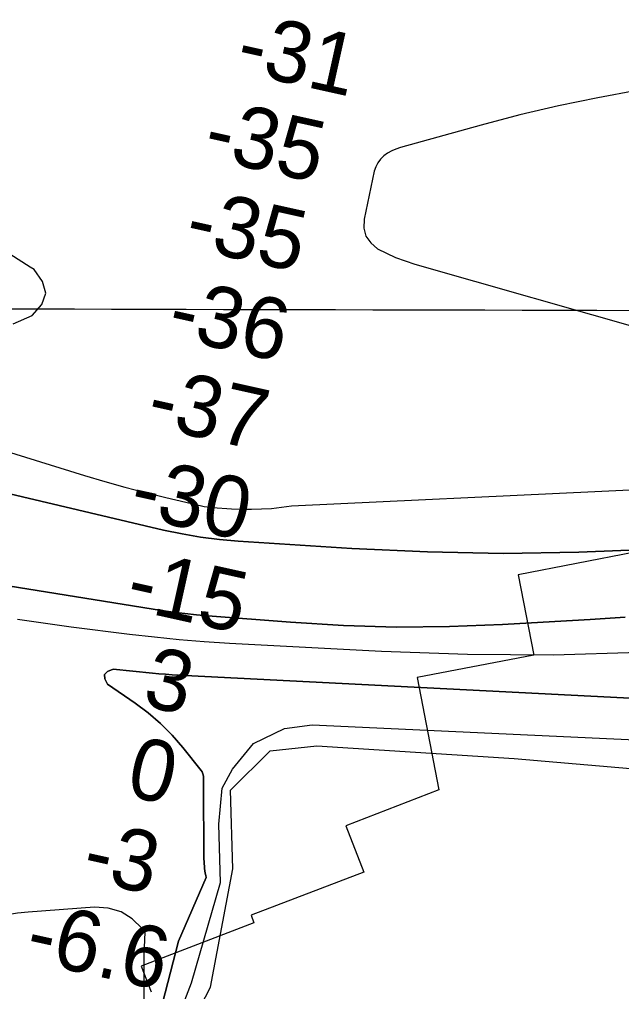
# Model space of a CAD drawing. Extents: x 3161615 to 3199515, y 867541 to 892976.
# Drawn here: x 3188892 to 3189551, y 878257 to 879321 of the extents above; entities that cross this region are included whole.
import ezdxf

# ---------------------------------------------------------------- set-up
doc = ezdxf.new("R2010")
doc.units = 0
for name, color, linetype in [('V-GRID-MAJR', 7, 'Continuous'), ('V-RIVR-RANG', 7, 'Continuous'), ('V-RRAP-RVMT', 7, 'Continuous'), ('V-TOPO-DPTH', 7, 'Continuous'), ('V-TOPO-MAJR', 7, 'Continuous'), ('V-TOPO-MINR', 7, 'Continuous'), ('V-TOPO-WATR', 7, 'Continuous')]:
    doc.layers.add(name, color=color, linetype=linetype)

msp = doc.modelspace()

# ---------------------------------------------------------------- linework, layer by layer
at = {"layer": 'V-GRID-MAJR'}
msp.add_spline([(3165838.644, 879070.158), (3171065.6580000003, 879053.813), (3176292.6750000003, 879038.2270000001), (3181519.694, 879023.402), (3186746.716, 879009.337), (3191973.739, 878996.033), (3197200.764, 878983.488), (3197200.765, 878983.488)], degree=3, dxfattribs=at)
at = {"layer": 'V-RRAP-RVMT'}
for p, q in [((3189565.0620000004, 878737.9829999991), (3189437.496000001, 878713.1959999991)), ((3189437.496000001, 878713.1959999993), (3189454.570000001, 878625.2389999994)), ((3189454.5700000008, 878625.2389999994), (3189326.954000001, 878600.6169999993)), ((3189326.954000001, 878600.616999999), (3189350.876000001, 878477.5729999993)), ((3189350.876000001, 878477.5729999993), (3189249.0130000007, 878438.148999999)), ((3189249.0130000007, 878438.148999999), (3189268.5090000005, 878387.773999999)), ((3189268.509000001, 878387.773999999), (3189145.2030000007, 878340.476999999)), ((3189148.2570000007, 878332.1869999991), (3189025.0790000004, 878284.8169999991)), ((3189145.2030000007, 878340.476999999), (3189148.2570000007, 878332.1869999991)), ((3189025.0790000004, 878284.8169999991), (3189036.0170000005, 878256.7379999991))]:
    msp.add_line(p, q, dxfattribs=at)
at = {"layer": 'V-TOPO-DPTH'}
for points in [[(3188203.1891735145, 879179.2378905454), (3188433.301359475, 878925.2373128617), (3188445.571534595, 878917.5798306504), (3188458.2858328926, 878910.6848433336), (3188471.2962133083, 878904.2981859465), (3188484.667643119, 878898.6978247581), (3188498.2204028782, 878893.6289504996), (3188512.0451575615, 878889.3573066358), (3188526.051242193, 878885.6171497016), (3189049.484469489, 878762.0639388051), (3189069.719366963, 878757.8251826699), (3189090.0565771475, 878754.2748056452), (3189110.5472563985, 878751.7569972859), (3189131.140248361, 878749.9275680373), (3189255.383497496, 878742.0529966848), (3189338.179173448, 878738.3195993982), (3189420.9799930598, 878736.5986324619), (3189503.788528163, 878737.8963110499), (3189586.602206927, 878741.2064199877)], [(3189586.602206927, 878741.2064199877), (3189503.788528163, 878737.8963110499), (3189420.9799930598, 878736.5986324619), (3189338.179173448, 878738.3195993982), (3189255.383497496, 878742.0529966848), (3189131.140248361, 878749.9275680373), (3189110.5472563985, 878751.7569972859), (3189090.0565771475, 878754.2748056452), (3189069.719366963, 878757.8251826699), (3189049.484469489, 878762.0639388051), (3188526.051242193, 878885.6171497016), (3188512.0451575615, 878889.3573066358), (3188498.2204028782, 878893.6289504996), (3188484.667643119, 878898.6978247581), (3188471.2962133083, 878904.2981859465), (3188458.2858328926, 878910.6848433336), (3188445.571534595, 878917.5798306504), (3188433.301359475, 878925.2373128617), (3188203.1891735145, 879179.2378905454)], [(3188479.070278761, 878972.2951769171), (3188962.946035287, 878821.8761231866), (3188985.0649386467, 878815.2596958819), (3189007.2705454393, 878808.961974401), (3189029.606207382, 878803.1423116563), (3189052.028572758, 878797.6413547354), (3189091.053715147, 878788.510154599), (3189094.0397863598, 878787.8898150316), (3189097.0406784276, 878787.3698706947), (3189100.0638017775, 878787.0005192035), (3189103.101745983, 878786.7315629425), (3189123.9832734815, 878785.4082979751), (3189134.9146295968, 878784.9585381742), (3189145.842590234, 878784.8314750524), (3189156.7654576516, 878785.18845695), (3189167.6849295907, 878785.8681355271), (3189178.5613347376, 878787.0403400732), (3189189.3839924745, 878788.5434552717), (3189868.827635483, 878820.881263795)], [(3188479.070278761, 878972.2951769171), (3188962.946035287, 878821.8761231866), (3188985.0649386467, 878815.2596958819), (3189007.2705454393, 878808.961974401), (3189029.606207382, 878803.1423116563), (3189052.028572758, 878797.6413547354), (3189091.053715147, 878788.510154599), (3189094.0397863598, 878787.8898150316), (3189097.0406784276, 878787.3698706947), (3189100.0638017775, 878787.0005192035), (3189103.101745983, 878786.7315629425), (3189123.9832734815, 878785.4082979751), (3189134.9146295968, 878784.9585381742), (3189145.842590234, 878784.8314750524), (3189156.7654576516, 878785.18845695), (3189167.6849295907, 878785.8681355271), (3189178.5613347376, 878787.0403400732), (3189189.3839924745, 878788.5434552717), (3189868.827635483, 878820.881263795)], [(3189554.769783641, 878666.6440336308), (3189516.243883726, 878664.3081813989), (3189477.7140027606, 878662.0366560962), (3189420.2718497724, 878658.7223437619), (3189362.2907585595, 878656.5620570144), (3189304.325865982, 878655.9768040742), (3189246.385271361, 878657.7541018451), (3189188.460875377, 878661.1064334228), (3189098.1130941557, 878668.1863299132), (3189085.3930775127, 878669.3381450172), (3189072.6974184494, 878670.6944916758), (3189060.0382957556, 878672.3576356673), (3189047.403530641, 878674.225311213), (3188690.8657579, 878731.3461501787)], [(3189554.769783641, 878666.6440336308), (3189516.243883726, 878664.3081813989), (3189477.7140027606, 878662.0366560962), (3189420.2718497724, 878658.7223437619), (3189362.2907585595, 878656.5620570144), (3189304.325865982, 878655.9768040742), (3189246.385271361, 878657.7541018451), (3189188.460875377, 878661.1064334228), (3189098.1130941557, 878668.1863299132), (3189085.3930775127, 878669.3381450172), (3189072.6974184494, 878670.6944916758), (3189060.0382957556, 878672.3576356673), (3189047.403530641, 878674.225311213), (3188690.8657579, 878731.3461501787)], [(3189048.388966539, 878244.0563978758), (3189065.964465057, 878312.1641532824), (3189096.0798038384, 878381.6029106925), (3189095.575594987, 878384.098144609), (3189095.1172046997, 878386.6011226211), (3189094.7275422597, 878389.1157167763), (3189094.3836983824, 878391.6380550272), (3189094.118763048, 878394.1690414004), (3189093.9129734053, 878396.7037903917), (3189093.795902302, 878399.2441833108), (3189093.7379768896, 878401.7883388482), (3189093.298547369, 878485.0604478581), (3189093.2521201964, 878488.6930684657), (3189093.1511895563, 878492.3245834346), (3189092.9174393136, 878494.077430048), (3189091.722366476, 878497.3145169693), (3189090.7610438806, 878498.7987572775), (3189070.5582953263, 878524.192966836), (3189058.76762427, 878537.7107065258), (3189046.246385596, 878550.4420646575), (3189032.629295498, 878561.9938504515), (3189018.2816377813, 878572.7592546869), (3188988.155947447, 878593.3020626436), (3188985.148641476, 878599.1140312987), (3188984.7291181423, 878603.9780742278), (3188988.1912687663, 878607.4202285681), (3188994.2412020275, 878609.9144571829), (3189015.9114785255, 878607.6573992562), (3189023.0453711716, 878606.9251404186), (3189030.1806724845, 878606.207092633), (3189037.318086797, 878605.5103614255), (3189044.456909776, 878604.8278412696), (3189051.60013504, 878604.2021755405), (3189058.747819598, 878603.6380805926), (3189065.9021930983, 878603.1663418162), (3189073.061025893, 878602.7561738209), (3189688.8577251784, 878571.4622313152)], [(3189688.8577251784, 878571.4622313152), (3189073.061025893, 878602.7561738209), (3189065.9021930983, 878603.1663418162), (3189058.747819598, 878603.6380805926), (3189051.60013504, 878604.2021755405), (3189044.456909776, 878604.8278412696), (3189037.318086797, 878605.5103614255), (3189030.1806724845, 878606.207092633), (3189023.0453711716, 878606.9251404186), (3189015.9114785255, 878607.6573992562), (3188994.2412020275, 878609.9144571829), (3188988.1912687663, 878607.4202285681), (3188984.7291181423, 878603.9780742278), (3188985.148641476, 878599.1140312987), (3188988.155947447, 878593.3020626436), (3189018.2816377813, 878572.7592546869), (3189032.629295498, 878561.9938504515), (3189046.246385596, 878550.4420646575), (3189058.76762427, 878537.7107065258), (3189070.5582953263, 878524.192966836), (3189090.7610438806, 878498.7987572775), (3189091.722366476, 878497.3145169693), (3189092.9174393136, 878494.077430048), (3189093.1511895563, 878492.3245834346), (3189093.2521201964, 878488.6930684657), (3189093.298547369, 878485.0604478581), (3189093.7379768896, 878401.7883388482), (3189093.795902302, 878399.2441833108), (3189093.9129734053, 878396.7037903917), (3189094.118763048, 878394.1690414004), (3189094.3836983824, 878391.6380550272), (3189094.7275422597, 878389.1157167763), (3189095.1172046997, 878386.6011226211), (3189095.575594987, 878384.098144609), (3189096.0798038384, 878381.6029106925), (3189065.964465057, 878312.1641532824), (3189048.388966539, 878244.0563978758)], [(3185917.3612426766, 877760.2649119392), (3186158.4746969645, 877745.7198556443), (3186674.762642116, 877703.865593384), (3187305.188926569, 877674.5519301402), (3187308.215647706, 877674.977304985), (3187425.4665777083, 877701.208771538), (3188410.1989931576, 877917.5982468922), (3188725.840560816, 878033.0666855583), (3189042.5555295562, 878149.1219312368), (3189100.986095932, 878261.7331430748), (3189125.4672609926, 878391.1748868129), (3189122.915072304, 878477.5008550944), (3189166.1252535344, 878520.5896541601), (3189217.3608707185, 878525.8993209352), (3189433.029411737, 878512.051905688), (3189721.475682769, 878487.2929126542)], [(3185917.3612426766, 877760.2649119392), (3186158.4746969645, 877745.7198556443), (3186674.762642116, 877703.865593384), (3187305.188926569, 877674.5519301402), (3187308.215647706, 877674.977304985), (3187425.4665777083, 877701.208771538), (3188410.1989931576, 877917.5982468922), (3188725.840560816, 878033.0666855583), (3189042.5555295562, 878149.1219312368), (3189100.986095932, 878261.7331430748), (3189125.4672609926, 878391.1748868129), (3189122.915072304, 878477.5008550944), (3189166.1252535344, 878520.5896541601), (3189217.3608707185, 878525.8993209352), (3189433.029411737, 878512.051905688), (3189721.475682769, 878487.2929126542)]]:
    msp.add_lwpolyline(points, dxfattribs=at)
at = {"layer": 'V-TOPO-MAJR'}
for points in [[(3189567.5439262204, 879243.1646058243), (3189524.584328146, 879235.3463600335), (3189481.828514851, 879226.607403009), (3189439.378378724, 879216.4873791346), (3189397.132027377, 879205.4466440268), (3189308.6901605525, 879180.7945524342), (3189303.8184791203, 879179.1180159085), (3189299.129439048, 879177.0811249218), (3189294.7143610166, 879174.5037022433), (3189290.4819243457, 879171.5659251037), (3189286.8732942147, 879168.0481071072), (3189283.846407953, 879164.1673957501), (3189281.692137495, 879159.7423443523), (3189280.119610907, 879154.9543995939), (3189268.8722997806, 879102.4552351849), (3189268.814091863, 879092.6607520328), (3189270.8952248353, 879083.8410824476), (3189276.1853691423, 879076.4836332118), (3189283.6148543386, 879070.1009975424), (3189293.449483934, 879065.098254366), (3189303.4744654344, 879060.5568348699), (3189313.7849747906, 879056.7074008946), (3189324.285836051, 879053.3192906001), (3189841.8267295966, 878905.6001354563)], [(3188884.787453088, 878987.8881801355), (3188905.901862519, 878996.9181793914), (3188916.1525221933, 879009.1194955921), (3188920.812517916, 879021.5285984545), (3188917.086517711, 879034.2493813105), (3188907.7698535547, 879047.1779508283), (3188903.617624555, 879049.974967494), (3188881.4618727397, 879064.1399470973)]]:
    msp.add_lwpolyline(points, dxfattribs=at)
at = {"layer": 'V-TOPO-MINR'}
for points in [[(3189586.602206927, 878741.2064199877), (3189503.788528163, 878737.8963110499), (3189420.9799930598, 878736.5986324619), (3189338.179173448, 878738.3195993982), (3189255.383497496, 878742.0529966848), (3189131.140248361, 878749.9275680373), (3189110.5472563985, 878751.7569972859), (3189090.0565771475, 878754.2748056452), (3189069.719366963, 878757.8251826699), (3189049.484469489, 878762.0639388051), (3188526.051242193, 878885.6171497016), (3188512.0451575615, 878889.3573066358), (3188498.2204028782, 878893.6289504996), (3188484.667643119, 878898.6978247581), (3188471.2962133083, 878904.2981859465), (3188458.2858328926, 878910.6848433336), (3188445.571534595, 878917.5798306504), (3188433.301359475, 878925.2373128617), (3188203.1891735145, 879179.2378905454)], [(3188479.070278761, 878972.2951769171), (3188962.946035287, 878821.8761231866), (3188985.0649386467, 878815.2596958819), (3189007.2705454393, 878808.961974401), (3189029.606207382, 878803.1423116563), (3189052.028572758, 878797.6413547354), (3189091.053715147, 878788.510154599), (3189094.0397863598, 878787.8898150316), (3189097.0406784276, 878787.3698706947), (3189100.0638017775, 878787.0005192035), (3189103.101745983, 878786.7315629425), (3189123.9832734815, 878785.4082979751), (3189134.9146295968, 878784.9585381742), (3189145.842590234, 878784.8314750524), (3189156.7654576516, 878785.18845695), (3189167.6849295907, 878785.8681355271), (3189178.5613347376, 878787.0403400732), (3189189.3839924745, 878788.5434552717), (3189868.827635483, 878820.881263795)], [(3188690.8657579, 878731.3461501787), (3189047.403530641, 878674.225311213), (3189060.0382957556, 878672.3576356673), (3189072.6974184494, 878670.6944916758), (3189085.3930775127, 878669.3381450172), (3189098.1130941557, 878668.1863299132), (3189188.460875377, 878661.1064334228), (3189246.385271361, 878657.7541018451), (3189304.325865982, 878655.9768040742), (3189362.2907585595, 878656.5620570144), (3189420.2718497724, 878658.7223437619), (3189477.7140027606, 878662.0366560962), (3189516.243883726, 878664.3081813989), (3189554.769783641, 878666.6440336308)], [(3188889.5305294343, 878664.4141055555), (3188948.4866297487, 878656.265257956), (3189012.140297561, 878648.2699883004), (3189039.4179009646, 878645.1381835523), (3189066.7303012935, 878642.3941575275), (3189094.094897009, 878640.2317995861), (3189121.4942896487, 878638.4572203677), (3189287.909104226, 878629.4558790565), (3189381.9712097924, 878626.2344505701), (3189476.003744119, 878625.4941108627), (3189569.9919215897, 878628.4754043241)], [(3189048.388966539, 878244.0563978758), (3189065.964465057, 878312.1641532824), (3189096.0798038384, 878381.6029106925), (3189095.575594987, 878384.098144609), (3189095.1172046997, 878386.6011226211), (3189094.7275422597, 878389.1157167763), (3189094.3836983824, 878391.6380550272), (3189094.118763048, 878394.1690414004), (3189093.9129734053, 878396.7037903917), (3189093.795902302, 878399.2441833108), (3189093.7379768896, 878401.7883388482), (3189093.298547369, 878485.0604478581), (3189093.2521201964, 878488.6930684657), (3189093.1511895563, 878492.3245834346), (3189092.9174393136, 878494.077430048), (3189091.722366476, 878497.3145169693), (3189090.7610438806, 878498.7987572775), (3189070.5582953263, 878524.192966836), (3189058.76762427, 878537.7107065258), (3189046.246385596, 878550.4420646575), (3189032.629295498, 878561.9938504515), (3189018.2816377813, 878572.7592546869), (3188988.155947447, 878593.3020626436), (3188985.148641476, 878599.1140312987), (3188984.7291181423, 878603.9780742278), (3188988.1912687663, 878607.4202285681), (3188994.2412020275, 878609.9144571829), (3189015.9114785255, 878607.6573992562), (3189023.0453711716, 878606.9251404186), (3189030.1806724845, 878606.207092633), (3189037.318086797, 878605.5103614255), (3189044.456909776, 878604.8278412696), (3189051.60013504, 878604.2021755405), (3189058.747819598, 878603.6380805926), (3189065.9021930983, 878603.1663418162), (3189073.061025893, 878602.7561738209), (3189688.8577251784, 878571.4622313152)], [(3187433.0897712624, 877725.8117667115), (3187609.536727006, 877765.0821642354), (3188171.2503237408, 877887.2071064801), (3188366.5037893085, 877924.3350493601), (3188725.0182130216, 878054.8246054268), (3188948.8662842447, 878125.0998440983), (3189024.0018704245, 878154.6753199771), (3189043.2361527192, 878170.3671828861), (3189080.066327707, 878266.3964966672), (3189111.681248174, 878376.4113410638), (3189110.041401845, 878440.1833793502), (3189113.599329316, 878479.4872909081), (3189124.984508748, 878500.4335555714), (3189147.731559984, 878528.3492900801), (3189181.8098917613, 878544.889951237), (3189212.2382142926, 878548.7155966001), (3189785.6862552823, 878522.3526904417)], [(3189029.367276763, 878321.8959144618), (3189026.111714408, 878326.1008482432), (3189015.1149761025, 878336.4976248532), (3189002.94974057, 878344.2642874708), (3188989.0317591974, 878348.0857790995), (3188973.945280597, 878349.2771567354), (3188901.200284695, 878343.7522648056), (3188889.7734579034, 878342.5754192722), (3188878.4139631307, 878340.9944255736), (3188867.155466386, 878338.8072096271), (3188855.964301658, 878336.2158455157), (3188844.799642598, 878333.4269142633), (3188833.6025711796, 878330.781280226)], [(3189028.149886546, 878237.5766227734), (3189028.2488516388, 878296.9226349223), (3189029.367276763, 878321.8959144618)]]:
    msp.add_lwpolyline(points, dxfattribs=at)
at = {"layer": 'V-TOPO-WATR'}
msp.add_lwpolyline([(3185917.3612426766, 877760.2649119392), (3186158.4746969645, 877745.7198556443), (3186674.762642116, 877703.865593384), (3187305.188926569, 877674.5519301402), (3187308.215647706, 877674.977304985), (3187425.4665777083, 877701.208771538), (3188410.1989931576, 877917.5982468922), (3188725.840560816, 878033.0666855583), (3189042.5555295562, 878149.1219312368), (3189100.986095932, 878261.7331430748), (3189125.4672609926, 878391.1748868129), (3189122.915072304, 878477.5008550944), (3189166.1252535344, 878520.5896541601), (3189217.3608707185, 878525.8993209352), (3189433.029411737, 878512.051905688), (3189721.475682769, 878487.2929126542)], dxfattribs=at)

# ---------------------------------------------------------------- texts
at = {"layer": 'V-RIVR-RANG'}
for s, p in [('-31', (3189126.5484976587, 879264.6318454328)), ('-35', (3189090.9545055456, 879170.1082286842)), ('-35', (3189070.5545055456, 879072.2112286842)), ('-36', (3189051.6995555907, 878973.9711727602)), ('-37', (3189028.724472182, 878876.6459326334)), ('-30', (3189010.126030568, 878778.3487007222)), ('-15', (3189005.9490560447, 878676.8496135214)), ('3', (3189024.6903238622, 878570.2618634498)), ('0', (3189006.60689893, 878471.8502795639)), ('-3', (3188958.1384897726, 878380.1854621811)), ('-6.6', (3188896.022138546, 878291.549972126))]:
    msp.add_text(s, height=67.00000000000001, rotation=347.48138888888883, dxfattribs=at).set_placement(p)

doc.saveas('drawing.dxf')
